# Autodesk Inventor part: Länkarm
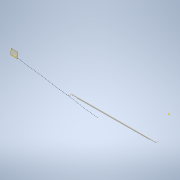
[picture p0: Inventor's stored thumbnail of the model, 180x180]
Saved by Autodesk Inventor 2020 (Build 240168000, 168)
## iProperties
Created: 2019-07
Part Number: Länkarm
Material: Generic
Document SubType Name: Modeling
Designer: cl
Density: 1 g/cm^3
Appearance: Default
Author: cl
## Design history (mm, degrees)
workplane "Work Plane1"
sketch "Sketch2"
  geometry: L1 (-203.247, -579.858)-(-1842.026, -588.393); L2 (-259.309, -580.15)-(-259.362, -570.15); L3 (-259.362, -570.15)-(-349.36, -570.619); L4 (-349.36, -570.619)-(-349.386, -565.619); L5 (-349.386, -565.619)-(-1732.105, -572.821); L6 (-1732.105, -572.821)-(-1732.079, -577.821); L7 (-1732.079, -577.821)-(-1822.078, -578.289); L8 (-1822.078, -578.289)-(-1822.026, -588.289); L9 (-1822.026, -588.289)-(-259.309, -580.15); C1 r 6 at (-1842.026, -588.393) reference; C2 r 6 at (-239.31, -580.046) reference
  constraints: 18 end point, 4 perpendicular, 3 point on line, 2 parallel, 1 coincident, 1 collinear
  dimensions: "d17" = 10 distance between parallel lines of L1 L3; "d18" = 90 distance of L2.end L3.end; "d23" = 90 distance of L6.end L7.end; "d24" = 5 distance between parallel lines of L5 L7; "d25" = 5 distance between parallel lines of L3 L5; "d68" = 20 distance from line of L8 L1.end; "d69" = 20 distance from line of C2.centre L2
revolve "Revolution2" sketch "Sketch2" stored, may be unused: angle "d27" = 90 deg
fillet "Fillet2" dims "d28" = 5
sketch "Sketch4"
  geometry: L1 (-1821.987, -595.789)-(-1841.987, -595.893); L2 (-1841.987, -595.893)-(-1842.065, -580.893); L3 (-1842.065, -580.893)-(-1822.065, -580.789); L4 (-1822.065, -580.789)-(-1821.987, -595.789); L5 (-259.257, -590.15)-(-259.362, -570.15) reference; L6 (-1821.974, -598.289)-(-1822.078, -578.289) reference; L7 (-259.257, -590.15)-(-259.362, -570.15) reference; L8 (-259.348, -572.65)-(-239.349, -572.546); L9 (-239.349, -572.546)-(-239.271, -587.546); L10 (-239.271, -587.546)-(-259.27, -587.65); C1 r 6 at (-214.321, -580.802) reference; 2 further points
  constraints: 14 end point, 6 perpendicular, 1 collinear, 1 point on line
  dimensions: "d42" = 20 distance of L1.start L1.end; "d43" = 15 distance of L1.end L2.end; "d51" = 2.5 distance from line of L6.start L1; "d52" = 20 distance of L8.start L8.end; "d53" = 15 distance of L8.end L9.end; "d54" = 90 deg angle of L8 L9 (derived); "d55" = 20 distance of L9.end L10.end; "d56" = 90 deg angle of L9 L10 (derived); "d57" = 2.5 distance from line of L5.end L8
extrude "Extrusion1" join sketch "Sketch4" stored distance "d32" = 4; taper "d33" = 0 deg
sketch "Sketch5"
  geometry: L1 (-239.271, -587.546)-(-239.349, -572.546) reference; C1 r 6 at (-52.936, -779.177) reference; C2 r 10 at (-239.31, -580.046)
  constraints: 1 centre point, 1 midpoint
  dimensions: "d58" = 20 diameter of C2
extrude "Extrusion2" join sketch "Sketch5" distance "d35" = 8; taper "d36" = 0 deg; dims "d37" = 48, "d38" = 0
sketch "Sketch6"
  geometry: L1 (-1842.065, -580.893)-(-1841.987, -595.893) reference; C1 r 10 at (-1842.026, -588.393); 1 further point
  constraints: 1 centre point, 1 midpoint
  dimensions: "d60" = 20 diameter of C1
extrude "Extrusion3" join sketch "Sketch6" distance "d61" = 48; taper "d63" = 0 deg; dims "d62" = 8, "d64" = 0
fillet "Fillet3" dims "d39" = 5
workplane "Work Plane2"
sketch "Sketch7"
  geometry: L1 (1538.345, -273.037)-(-45, -83); C1 r 6 at (-45, -83) reference; C2 r 6 at (1538.345, -273.037) reference; 1 further point
  constraints: 2 end point
  node "Reference9"
  node "Reference10"
body "Solid2"
node "Reference6"
node "Projected Loop1"
node "Reference13"
node "Reference14"
other parameters: "Fönsterhöjd" = 862
